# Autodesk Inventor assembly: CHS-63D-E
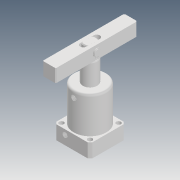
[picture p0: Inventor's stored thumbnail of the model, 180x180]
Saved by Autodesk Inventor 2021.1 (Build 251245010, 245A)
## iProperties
Created: 2019-05
Part Number: CHS-63D-E
Description: STEP AP203
Document SubType Name: Assembly
Designer: user
Title: chs-63d-e_asm.STEP
Revision Number: ÈÎºÎ
Sending System: SolidWorks 2017
Preprocessor: SwSTEP 2.0
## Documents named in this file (6)
- D:\Vault_2016\Projekty\Clamptek\Hydraulic\CHS\CHS-63\Inventor\CHS-63D-E\CHS-63D-E.iam
- D:\Vault_2016\Projekty\Clamptek\Hydraulic\CHS\CHS-63\Inventor\CHS-63D-E\CHS-63-03-E.ipt
- D:\Vault_2016\Projekty\Clamptek\Hydraulic\CHS\CHS-63\Inventor\CHS-63D-E\CHS-63D-01_5.ipt
- D:\Vault_2016\Projekty\Clamptek\Hydraulic\CHS\CHS-63\Inventor\CHS-63D-E\¶ÌÏú.ipt
- D:\Vault_2016\Projekty\Clamptek\Hydraulic\CHS\CHS-63\Inventor\CHS-63D-E\¿¨»É.ipt
- D:\Vault_2016\Projekty\Clamptek\Hydraulic\CHS\CHS-63\Inventor\CHS-63D-E\CHS-63D-E»îÈû¸Ë.ipt
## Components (6 placed, 6 different names)
1. CHS-63-03-E_1
2. CHS-63D-01_5_2
3. ¶ÌÏú_3
4. ¿¨»É_4
5. CHS-63D-E»îÈû¸Ë_5
6. ¿¨»É_6
